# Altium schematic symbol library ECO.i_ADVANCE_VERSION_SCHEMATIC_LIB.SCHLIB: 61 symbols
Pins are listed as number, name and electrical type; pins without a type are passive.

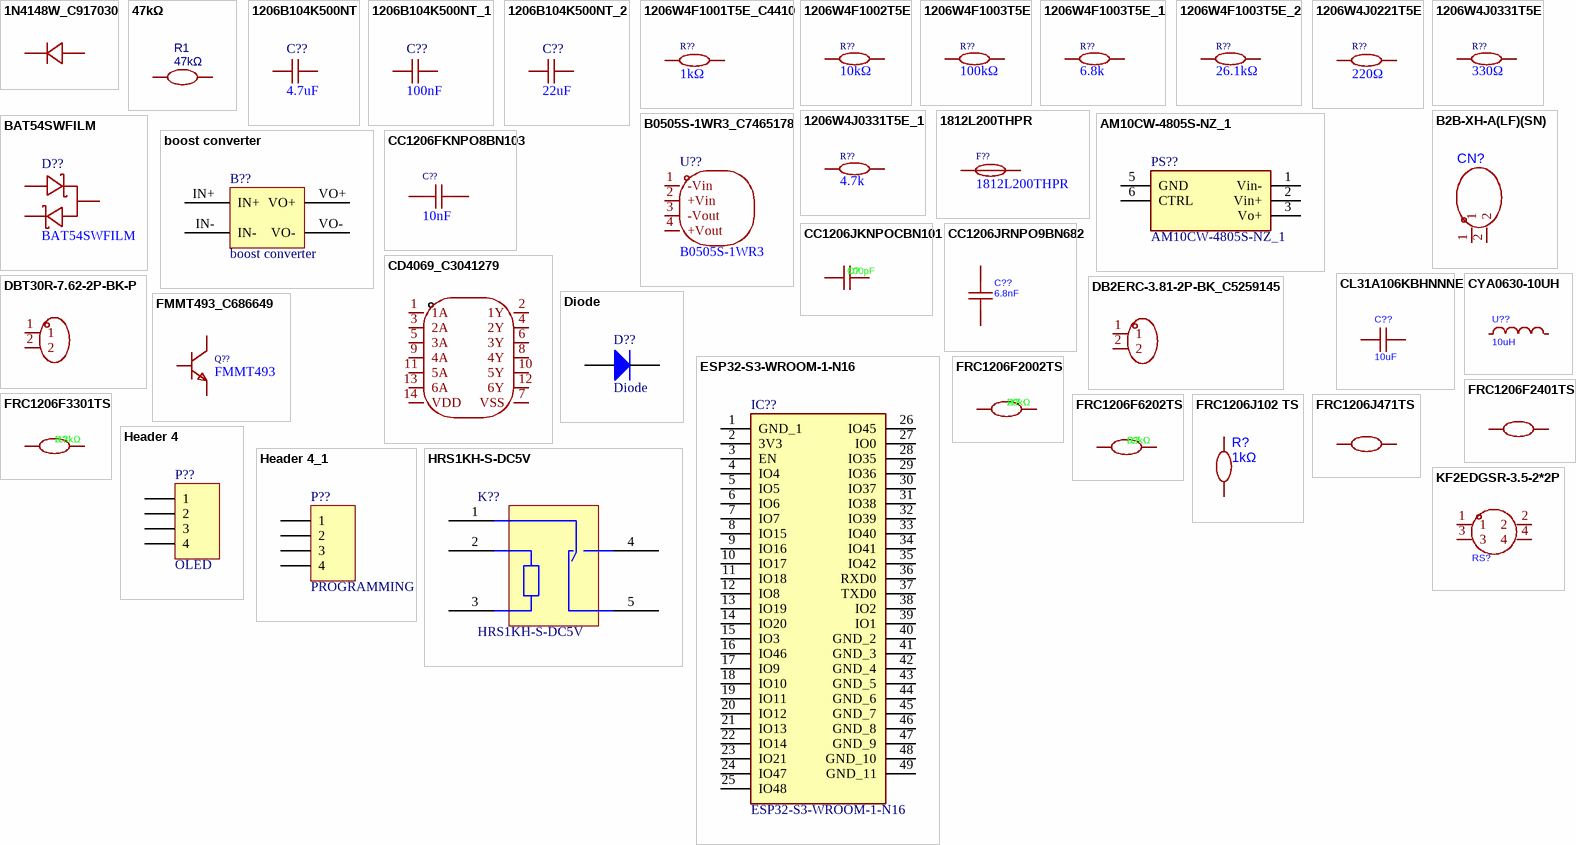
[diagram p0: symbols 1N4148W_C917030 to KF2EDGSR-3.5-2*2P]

## 1N4148W_C917030
designator D?, comment 1N4148W  (value not drawn)
Manufacturer: JSMSEMI(杰盛微); Symbol: 1N4148W_C917030; Add into BOM: yes; Diode Configuration: Independent; Voltage - Forward(Vf@If): 1.25V@150mA; Voltage - DC Reverse(Vr): 100V; Current - Rectified: 300mA; Pd - Power Dissipation: 400mW; Reverse Leakage Current (Ir): 1uA@75V; Reverse Recovery Time (trr): 8ns; Operating Junction Temperature Range: -55℃~+150℃@(Tj); Non-Repetitive Peak Forward Surge Current: 4A
footprint SOD-123_L2.8-W1.8-LS3.7-RD-1
pins: 1 C, 2 A

## 47kΩ
designator R1
Manufacturer: FOJAN(富捷); Manufacturer Part: FRC1206J473 TS; nameAlias: Value; Contributor: lcsc
footprint RESC3216X75N
pins: 1, 2

## 1206B104K500NT
designator C??, comment 4.7uF
Manufacturer: FH(风华); Symbol: 1206B104K500NT; Add into BOM: yes; Tolerance: ±10%
footprint C1206
3D model C1206_L3.2-W1.6-H1.3
pins: 1, 2

## 1206B104K500NT_1
designator C??, comment 100nF
Manufacturer: FH(风华); Symbol: 1206B104K500NT; Add into BOM: yes; Tolerance: ±10%
footprint C1206
3D model C1206_L3.2-W1.6-H1.3
pins: 1, 2

## 1206B104K500NT_2
designator C??, comment 22uF
Manufacturer: FH(风华); Manufacturer Part: 1206X226M250NT1206B104K500NT; Symbol: 1206X226M250NT; Device: 1206B104K500NT; Add into BOM: yes; Tolerance: ±10%
footprint C1206
3D model C1206_L3.2-W1.6-H1.3
pins: 1, 2

## 1206W4F1001T5E_C4410
designator R??, comment 1kΩ
Manufacturer: UNI-ROYAL(厚声); Symbol: 1206W4F1001T5E; Device: 1206W4F1001T5E_C4410; Add into BOM: yes; Tolerance: ±1%
3D model R1206_L3.2-W1.6-H0.6
footprint RESC3216X75N
pins: 1, 2

## 1206W4F1002T5E
designator R??, comment 10kΩ
Manufacturer: UNI-ROYAL(厚声); Symbol: 1206W4F1002T5E; Add into BOM: yes; Tolerance: ±1%; Temperature Coefficient: ±100ppm/℃
3D model R1206_L3.2-W1.6-H0.6
footprint RESC3216X75N
pins: 1, 2

## 1206W4F1003T5E
designator R??, comment 100kΩ
Manufacturer: UNI-ROYAL(厚声); Symbol: 1206W4F1003T5E; Add into BOM: yes; Tolerance: ±1%; Temperature Coefficient: ±100ppm/℃
3D model R1206_L3.2-W1.6-H0.6
footprint RESC3216X75N
pins: 1, 2

## 1206W4F1003T5E_1
designator R??, comment 6.8k
Manufacturer: UNI-ROYAL(厚声); Symbol: 1206W4F1003T5E; Add into BOM: yes; Tolerance: ±1%; Temperature Coefficient: ±100ppm/℃
3D model R1206_L3.2-W1.6-H0.6
footprint RESC3216X75N
pins: 1, 2

## 1206W4F1003T5E_2
designator R??, comment 26.1kΩ
Manufacturer: UNI-ROYAL(厚声); Symbol: 1206W4F1003T5E; Value: 26.1k; Add into BOM: yes; Tolerance: ±1%; Temperature Coefficient: ±100ppm/℃
3D model R1206_L3.2-W1.6-H0.6
footprint RESC3216X75N
pins: 1, 2

## 1206W4J0221T5E
designator R??, comment 220Ω
Manufacturer: UNI-ROYAL(厚声); Symbol: 1206W4J0221T5E; Add into BOM: yes; Tolerance: ±5%; Temperature Coefficient: ±100ppm/℃
3D model R1206_L3.2-W1.6-H0.6
footprint RESC3216X75N
pins: 1, 2

## 1206W4J0331T5E
designator R??, comment 330Ω
Manufacturer: UNI-ROYAL(厚声); Symbol: 1206W4J0331T5E; Add into BOM: yes; Tolerance: ±5%; Temperature Coefficient: ±100ppm/℃
3D model R1206_L3.2-W1.6-H0.6
footprint RESC3216X75N
pins: 1, 2

## 1206W4J0331T5E_1
designator R??, comment 4.7k
Manufacturer: UNI-ROYAL(厚声); Manufacturer Part: 1206W4J0472T5E; Symbol: 1206W4J0331T5E; Add into BOM: yes; Tolerance: ±5%; Temperature Coefficient: ±100ppm/℃
3D model R1206_L3.2-W1.6-H0.6
footprint RESC3216X75N
pins: 1, 2

## 1812L200THPR
designator F??
Manufacturer: Littelfuse(美国力特); Add into BOM: yes; Operating Voltage (Max): 8V; Current Rating (Max): 100A; Hold Current: 2A; Trip Current: 3.5A; Resistance - Initial (Ri) (Min): 20mΩ; Resistance - Post Trip (R1) (Max): 70mΩ; Maximum Time to Trip: 2s
3D model F1812_L4.5-W3.2-H1.0
footprint 1812L010DR
pins: 1, 2

## AM10CW-4805S-NZ_1
designator PS??
Power Supply
footprint PS1
pins: 1 Vin-, 2 Vin+, 3 Vo+, 5 GND, 6 CTRL

## B2B-XH-A(LF)(SN)
designator CN?  (value not drawn)
Manufacturer: JST; Add into BOM: yes; Pins Structure: 1x2P; Pitch: 2.5mm; Reference Series: XH; Number of PINs Per Row: 2; Current Rating: 3A; Voltage Rating: 250V; Plastic Material: PA66; Flame Retardant Rating: UL94V-0; Supplementary Features: K Pin; Z-Height of the Board: 7mm; X-Length of Bottom Edge on Board (Spacing Line): 7.4mm; Y-Width of Bottom Edge on Board: 5.75mm
footprint CONN-TH_B2B-XH-A-LF-SN
pins: 1, 2

## B0505S-1WR3_C7465178
designator U??, comment B0505S-1WR3
Manufacturer: EVISUN(易成); Symbol: B0505S-1WR3_C7465178; Add into BOM: yes; Number of channel: 1; Power: 1W; input voltage (Vdc): 4.5V~5.5V; Conversion Efficiency: 86%; Output Voltage: 5V; Output Current (Max): 200mA; Maximum Capacitive Load: 2400uF; Insulated Voltage: 1.5kV
3D model PWRM-TH_B0505S-1WR3
footprint TME0512S
pins: 1 -Vin, 2 +Vin, 3 -Vout, 4 +Vout

## BAT54SWFILM
designator D??
Manufacturer: ST(意法半导体); Add into BOM: yes; Diode Configuration: 1对串联式; Forward Voltage (Vf@If): 900mV@100mA; Reverse Voltage (Vr): 40V; Average Rectified Current (Io): 300mA; Reverse Leakage Current (Ir): 1uA@30V
3D model SOT-323-3_L2.0-W1.3-H1.0-LS2.1-P1.30
footprint SOT65P210X110-3N (BAT54SWFILM)
pins: 1, 2, 3

## boost converter
designator B??
footprint B1
pins: IN+, IN-, VO+, VO-

## CC1206FKNPO8BN103
designator C??, comment 10nF
Manufacturer: YAGEO(国巨); Symbol: CC1206FKNPO8BN103; Add into BOM: yes; Tolerance: ±1%
footprint C1206
3D model C1206_L3.2-W1.6-H1.3
pins: 1, 2

## CC1206JKNPOCBN101
designator C?, comment 100pF
Manufacturer: YAGEO(国巨); Symbol: CC1206JKNPOCBN101; Add into BOM: yes; Tolerance: ±5%
footprint C1206
pins: 1, 2

## CC1206JRNPO9BN682
designator C??, comment 6.8nF
Manufacturer: YAGEO(国巨); Symbol: CC1206JRNPO9BN682; Add into BOM: yes; Tolerance: ±5%
footprint C1206
3D model C1206_L3.2-W1.6-H1.3
pins: 1, 2

## CD4069_C3041279
designator U?, comment CD4069  (value not drawn)
Manufacturer: Slkor(萨科微); Symbol: CD4069_C3041279; Add into BOM: yes; Supply Voltage(Single): 3V~15V; Supply Current (Max): 1uA; Number of Circuits: 6; Number of Inputs: 1
footprint SOP-14_L8.8-W3.9-P1.27-LS6.0-BL
pins: 1 1A, 2 1Y, 3 2A, 4 2Y, 5 3A, 6 3Y, 7 VSS, 8 4Y, 9 4A, 10 5Y, 11 5A, 12 6Y, 13 6A, 14 VDD

## CL31A106KBHNNNE
designator C??, comment 10uF
Manufacturer: SAMSUNG(三星); Symbol: CL31A106KBHNNNE; Add into BOM: yes; Tolerance: ±10%
footprint C1206
3D model C1206_L3.2-W1.6-H1.3
pins: 1, 2

## CYA0630-10UH
designator U??, comment 10uH
Manufacturer: SHOU HAN(首韩); Symbol: CYA0630-10UH; Add into BOM: yes; Tolerance: ±20%
footprint IND-SMD_L7.2-W6.6_GPSR07X0
pins: 1, 2

## DB2ERC-3.81-2P-BK_C5259145
designator U?, comment DB2ERC-3.81-2P-BK  (value not drawn)
Manufacturer: DORABO(地博电气); Symbol: DB2ERC-3.81-2P-BK_C5259145; Add into BOM: yes; Number of Positions or Pins: 1x2P; Pitch: 3.81mm; Number of PINs Per Row: 2; Current Rating: 8A; Voltage Rating (Max): 300V
footprint CONN-TH_2P-P3.81_DB2ERC-3.81-2P-BK
pins: 1, 2

## DBT30R-7.62-2P-BK-P
designator U?  (value not drawn)
Manufacturer: DORABO(地博电气); Add into BOM: yes; Barrier Type: 2-Side; Pitch: 7.62mm; Number of Positions or Pins: 1x2P; Number of PINs Per Row: 2; Current Rating: 17.5A; Voltage Rating (Max): 450V; Wire Gauge - AWG: 14~22; Wire Gauge - mm2: 1.5
footprint CONN-TH_2P-P7.62_DBT30R-7.62-2P
pins: 1, 2

## Diode
designator D??
Default Diode
simulation model DIODE (Diode)
signal-integrity model Diode
footprint diode_in
pins: 1 A, 2 K

## ESP32-S3-WROOM-1-N16
designator IC??
Integrated Circuit; Manufacturer_Name: Espressif Systems
footprint ESP32S3WROOM1N16
pins: 1 GND_1, 2 3V3, 3 EN, 4 IO4, 5 IO5, 6 IO6, 7 IO7, 8 IO15, 9 IO16, 10 IO17, 11 IO18, 12 IO8, 13 IO19, 14 IO20, 15 IO3, 16 IO46, 17 IO9, 18 IO10, 19 IO11, 20 IO12, 21 IO13, 22 IO14, 23 IO21, 24 IO47, 25 IO48, 26 IO45, 27 IO0, 28 IO35, 29 IO36, 30 IO37, 31 IO38, 32 IO39, 33 IO40, 34 IO41, 35 IO42, 36 RXD0, 37 TXD0, 38 IO2, 39 IO1, 40 GND_2, 41 GND_3, 42 GND_4, 43 GND_5, 44 GND_6, 45 GND_7, 46 GND_8, 47 GND_9, 48 GND_10, 49 GND_11

## FMMT493_C686649
designator Q??, comment FMMT493
Manufacturer: PJSEMI(平晶微); Symbol: FMMT493_C686649; Add into BOM: yes; DC Current Gain (hFE@Ic,Vce): 300; Transition Frequency (fT): 150MHz; Collector Cut-Off Current (Icbo): 100nA; Collector-Emitter Saturation Voltage (VCE(sat)@Ic,Ib): 600mV@1A,100mA
3D model SOT-23-3P_L2.9-W1.3-H1.0-LS2.4-P0.95
footprint SOT91P240X120-3N
pins: 1 B, 2 E, 3 C

## FRC1206F2002TS
designator R?, comment 20kΩ
Manufacturer: FOJAN(富捷); Symbol: FRC1206F2002TS; Add into BOM: yes; Tolerance: ±1%; Power(Watts): 250mW; Voltage-Supply(Max): 200V; Temperature Coefficient: ±100ppm/℃
footprint RESC3216X75N
pins: 1, 2

## FRC1206F2401TS
designator R?, comment 2.4kΩ  (value not drawn)
Manufacturer: FOJAN(富捷); Symbol: FRC1206F2401TS; Add into BOM: yes; Tolerance: ±1%; Power(Watts): 250mW; Voltage-Supply(Max): 200V; Temperature Coefficient: ±100ppm/℃
footprint RESC3216X75N
pins: 1, 2

## FRC1206F3301TS
designator R?, comment 3.3kΩ
Manufacturer: FOJAN(富捷); Symbol: FRC1206F3301TS; Add into BOM: yes; Tolerance: ±1%; Power(Watts): 250mW; Voltage-Supply(Max): 200V; Temperature Coefficient: ±100ppm/℃
footprint RESC3216X75N
pins: 1, 2

## FRC1206F6202TS
designator R?, comment 62kΩ
Manufacturer: FOJAN(富捷); Symbol: FRC1206F6202TS; Add into BOM: yes; Tolerance: ±1%; Power(Watts): 250mW; Voltage-Supply(Max): 200V; Temperature Coefficient: ±100ppm/℃
footprint RESC3216X75N
pins: 1, 2

## FRC1206J102 TS
designator R?, comment 1kΩ
Manufacturer: FOJAN(富捷); Symbol: FRC1206J102 TS; Add into BOM: yes; Tolerance: ±5%; Power(Watts): 250mW; Voltage-Supply(Max): 200V; Temperature Coefficient: ±100ppm/℃
footprint RESC3216X75N
pins: 1, 2

## FRC1206J471TS
designator R?, comment 470Ω  (value not drawn)
Manufacturer: FOJAN(富捷); Symbol: FRC1206J471TS; Add into BOM: yes; Tolerance: ±5%; Power(Watts): 250mW; Voltage-Supply(Max): 200V; Temperature Coefficient: ±100ppm/℃
footprint RESC3216X75N
pins: 1, 2

## Header 4
designator P??, comment OLED
Header, 4-Pin
footprint HDR1X4 (Connector; Header; 4 Position)
signal-integrity model Connector
pins: 1, 2, 3, 4

## Header 4_1
designator P??, comment PROGRAMMING
Header, 4-Pin
footprint HDR1X4 (Connector; Header; 4 Position)
signal-integrity model Connector
pins: 1, 2, 3, 4

## HRS1KH-S-DC5V
designator K??
footprint RELAY-TH_HRS1KH-S-DCXXX
pins: 1 31, 2, 3, 4, 5

## KF2EDGSR-3.5-2*2P
designator RS?  (value not drawn)
Manufacturer: KEFA(科发); Add into BOM: yes; Connector Type: Receptacle-Close; Structure: 2x2P; Pitch: 3.5mm; Number of PINs Per Row: 2; Current Rating (Max): 10A; Voltage Rating (Max): 300V
footprint CONN-TH_4P-P3.50_KEFA_KF2EDGSR-3.5-2X2P
3D model CONN-TH_4P-P3.50_KEFA_KF2EDGSR-3.5-2X2P
pins: 1, 2, 3, 4

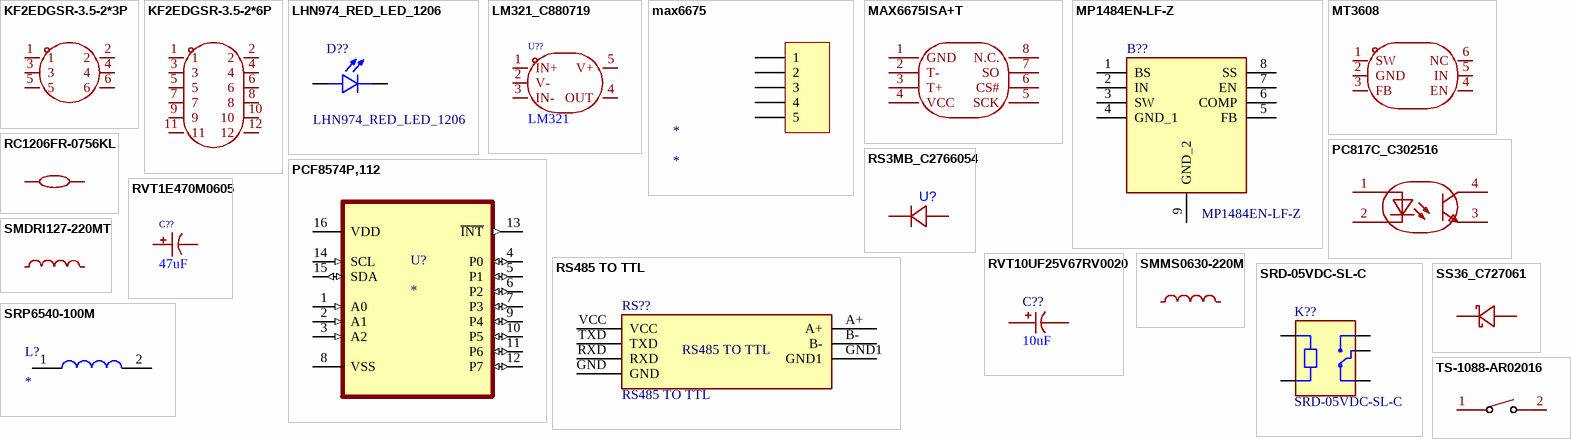
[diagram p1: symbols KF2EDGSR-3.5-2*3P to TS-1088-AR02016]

## KF2EDGSR-3.5-2*3P
designator CN?  (value not drawn)
Manufacturer: KEFA(科发); Add into BOM: yes; Connector Type: Board Side/Socket - Closed; Number of Positions or Pins: 2x3P; Pitch: 3.5mm; Number of PINs Per Row: 3; Current Rating: 10A; Voltage Rating (Max): 300V
footprint CONN-TH_6P-P3.50_KEFA_KF2EDGSR-3.5-2X3P
pins: 1, 2, 3, 4, 5, 6

## KF2EDGSR-3.5-2*6P
designator CN?  (value not drawn)
Manufacturer: KEFA(科发); Add into BOM: yes; Connector Type: Receptacle-Close; Structure: 2x6P; Pitch: 3.5mm; Number of PINs Per Row: 6; Current Rating (Max): 10A; Voltage Rating (Max): 300V
footprint CONN-TH_12P-P3.50_KEFA_KF2EDGSR-3.5-2X6P
3D model CONN-TH_12P-P3.50_KEFA_KF2EDGSR-3.5-2X6P
pins: 1, 2, 3, 4, 5, 6, 7, 8, 9, 10, 11, 12

## LHN974_RED_LED_1206
designator D??
2.6 V Red LED SMD; MF: Osram; MP: LHN974 RED LED 1206
footprint LEDC3216X120N
pins: NEG, POS

## LM321_C880719
designator U??, comment LM321
Manufacturer: Slkor(萨科微); Symbol: LM321_C880719; Add into BOM: yes; Common Mode Rejection Ratio (CMRR): 90dB; Slew Rate(SR): 0.4V/us
3D model SOT-23-5_L2.9-W1.6-P0.95-LS2.8-BL
footprint SOT95P280X145-5N
pins: 1 IN+, 2 V-, 3 IN-, 4 OUT, 5 V+

## max6675
designator *
footprint HDR1X5 (Connector; Header; 5 Position)
pins: 1, 2, 3, 4, 5

## MAX6675ISA+T
designator U?  (value not drawn)
Manufacturer: ADI(亚德诺)/MAXIM(美信); Add into BOM: yes; Resolution: 12; Voltage - Supply: 3V~5.5V; Interface Type: SPI; Chip Type Parameters/Description: Thermocouple to Digital Converter
footprint SOIC-8_L5.0-W4.0-P1.27-LS6.0-BL
pins: 1 GND, 2 T-, 3 T+, 4 VCC, 5 SCK, 6 CS#, 7 SO, 8 N.C.

## MP1484EN-LF-Z
designator B??
Switching Voltage Regulators 3A, 18V Sync Step-Down DCDC; Manufacturer_Name: Monolithic Power Systems (MPS)
footprint SOIC127P600X170-9N
pins: 1 BS, 2 IN, 3 SW, 4 GND_1, 5 FB, 6 COMP, 7 EN, 8 SS, 9 GND_2

## MT3608
designator U?  (value not drawn)
Manufacturer: 西安航天民芯; Add into BOM: yes; Function: Boost; Output Type: Adjustable; Voltage - Supply: 2V~24V; Output Current: 2A; Frequency - Switching: 1.2MHz; Synchronous Rectifier: No; Number of Outputs: 1; Quiescent Current: 100uA；1.6mA; Switch tube (built-in/external): Built-in
footprint SOT-23-6_L2.9-W1.6-P0.95-LS2.8-BL
pins: 1 SW, 2 GND, 3 FB, 4 EN, 5 IN, 6 NC

## PC817C_C302516
designator U?, comment PC817C  (value not drawn)
Manufacturer: AOTE(奥特); Symbol: PC817C_C20612594; Add into BOM: yes; Input voltage type: DC; Forward Voltage: 1.4V; Output Current: 50mA; Isolation Voltage(rms): 5kV; Reverse Voltage: 6V; Number of Outputs: 1; Collector-Emitter Saturation Voltage (Vce(sat)@Ic,IF): 200mV@1mA,20mA
footprint DIP762W60P254L460H455Q4N
pins: 1 A, 2 C, 3 E, 4 COLLECTOR

## PCF8574P,112
designator U?
Remote 8-bit I/O expander for I2C-bus; MP: PCF8574P-112
footprint DIP254P762X420-16
pins: 1 A0 (in), 2 A1 (in), 3 A2 (in), 4 P0 (io), 5 P1 (io), 6 P2 (io), 7 P3 (io), 8 VSS, 9 P4 (io), 10 P5 (io), 11 P6 (io), 12 P7 (io), 13 ~{INT} (out), 14 SCL (in), 15 SDA (io), 16 VDD (power)

## RC1206FR-0756KL
designator R?, comment 56kΩ  (value not drawn)
Manufacturer: YAGEO(国巨); Symbol: RC1206FR-0756KL; Add into BOM: yes; Tolerance: ±1%; Power(Watts): 250mW; Temperature Coefficient: ±100ppm/℃
footprint RESC3216X75N
pins: 1, 2

## RS3MB_C2766054
designator U?, comment RS3MB  (value not drawn)
Manufacturer: WPMtek(维攀); Symbol: RS3MB_C2766054; Add into BOM: yes; Voltage - Forward(Vf@If): 1.3V@3A; Voltage - DC Reverse(Vr): 1kV; Current - Rectified: 3A; Reverse Leakage Current (Ir): 5uA@1000V; Reverse Recovery Time (trr): 500ns
footprint diode_in
pins: 1 K, 2 A

## RS485 TO TTL
designator RS??
footprint RS485 TO TTL
pins: A+, B-, GND, GND1, RXD, TXD, VCC (power)

## RVT1E470M0605
designator C??, comment 47uF
Convert to PCB: yes; Tolerance: ±20%; Lifetime @ Temp: 2000hrs@105℃
3D model CAP-SMD_BD6.3-L6.6-W6.6-FD
footprint CAPAE1030X1050N
pins: 1, 2

## RVT10UF25V67RV0020
designator C??, comment 10uF
Manufacturer: KNSCHA(科尼盛); Symbol: RVT10UF25V67RV0020; Add into BOM: yes; Tolerance: ±20%; Ripple Current: 21mA@120Hz; Lifetime @ Temp: 2000hrs@105℃
3D model CAP-SMD_L5.3-W5.3-H5.3-LS5.9
footprint WCAP-ASLI_D5H5.5 (Aluminium Electrolytic V-Chip SMT Capacitors, 5x5.5mm)
pins: 1, 2

## SMDRI127-220MT
designator L?, comment 22uH  (value not drawn)
Manufacturer: SXN(顺翔诺); Symbol: SMDRI127-220MT; Add into BOM: yes; Tolerance: ±20%; Current - Saturation(Isat): 7A; Type: Shielded inductor
footprint IND-SMD_L12.3-W12.3_SMDRI127
pins: 1, 2

## SMMS0630-220M
designator L?, comment 22uH  (value not drawn)
Manufacturer: SXN(顺翔诺); Symbol: SMMS0630-220M; Add into BOM: yes; Tolerance: ±20%; Current - Saturation(Isat): 3.5A; DC Resistance(DCR): 135mΩ
footprint IND-SMD_L7.3-W6.6_MHCI06030
pins: 1, 2

## SRD-05VDC-SL-C
designator K??
5V Trigger Relay Module For Arduino And Raspberry Pi 5V Trigger Relay Module For Arduino And Raspberry Pi; MF: Songle Relay
footprint RELAY_SRD-05VDC-SL-C
pins: A1, A2, COM, NC, NO

## SRP6540-100M
designator L?
Inductor; Manufacturer_Name: Bourns; Manufacturer_Part_Number: SRP6540-100M
footprint SRP6540
pins: 1, 2

## SS36_C727061
designator D?, comment SS36  (value not drawn)
Manufacturer: TWGMC(台湾迪嘉); Symbol: SS36_C727061; Add into BOM: yes; Diode Configuration: Independent; Voltage - Forward(Vf@If): 700mV@3A; Voltage - DC Reverse(Vr): 60V; Current - Rectified: 3A; Reverse Leakage Current (Ir): 500uA; Operating Junction Temperature Range: -55℃~+125℃
footprint SMA_L4.4-W2.6-LS5.0-RD
3D model SMA_L4.4-W2.6-LS5.0-RD
pins: 1 K, 2 A

## TS-1088-AR02016
designator SW??  (value not drawn)
Manufacturer: XUNPU(讯普); Add into BOM: yes; Circuit: SPST; Actuator Style: Round Button; Operating Force: 160gf; Switch Length: 4mm; Switch Width: 3mm; Switch Height: 2mm; Strike Gundam: 不带; Contact Current: 50mA; Voltage Rating (DC): 12V; Insulation Resistance: 100MΩ; Actuator/Cap Color: Black; Pin Style: SMDSplicing; Mechanical Life: 10万次
footprint SW-SMD_L3.9-W3.0-P4.45
3D model SW-SMD_L3.9-W2.9-H2.0-LS4.8
pins: 1, 2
